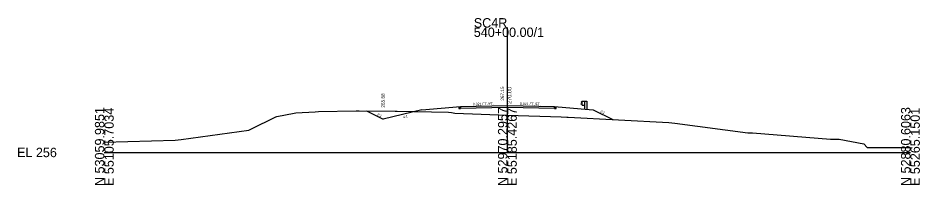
# Model space of a CAD drawing. Extents: x 9740 to 17409, y 8856 to 28416.
# Drawn here: x 11740.2 to 12008.7, y 20861.7 to 20911.5 of the extents above; entities that cross this region are included whole.
import ezdxf

# ---------------------------------------------------------------- set-up
doc = ezdxf.new("R2010")
doc.units = 0
for name, color, linetype in [('Level 10', 7, 'Continuous'), ('Level 11', 7, 'Continuous'), ('Level 12', 7, 'Continuous'), ('Level 24', 7, 'Continuous'), ('Level 32', 7, 'Continuous'), ('Level 33', 7, 'Continuous'), ('Level 59', 7, 'Continuous'), ('Level 6', 7, 'Continuous'), ('Level 60', 7, 'Continuous'), ('Level 63', 7, 'Continuous'), ('Level 7', 7, 'Continuous')]:
    doc.layers.add(name, color=color, linetype=linetype)

msp = doc.modelspace()

# ---------------------------------------------------------------- linework, layer by layer
at = {"layer": 'Level 11'}
for p, q in [((11871.85, 20884.79), (11871.35, 20884.78)), ((11871.35, 20884.78), (11871.35, 20884.44)), ((11871.35, 20884.44), (11871.85, 20884.45)), ((11871.85, 20885.09), (11871.85, 20884.79)), ((11899.85, 20884.79), (11899.85, 20885.09)), ((11900.35, 20884.78), (11899.85, 20884.79)), ((11899.85, 20884.45), (11900.35, 20884.44)), ((11900.35, 20884.44), (11900.35, 20884.78))]:
    msp.add_line(p, q, dxfattribs=at)
at = {"layer": 'Level 12'}
for p, q in [((11885.85, 20884.74), (11871.85, 20884.45)), ((11899.85, 20884.45), (11885.85, 20884.74))]:
    msp.add_line(p, q, dxfattribs=at)
at = {"layer": 'Level 24'}
for p, q in [((11908.12, 20886.6), (11907.85, 20886.4)), ((11908.12, 20885.51), (11908.12, 20886.67)), ((11908.12, 20886.67), (11908.79, 20886.67)), ((11908.79, 20886.67), (11908.79, 20884.34)), ((11908.79, 20886.67), (11909.46, 20886.67)), ((11909.46, 20886.67), (11909.46, 20884.29)), ((11907.85, 20886.4), (11907.85, 20886.35)), ((11907.85, 20886.35), (11908.12, 20886.15)), ((11907.85, 20885.83), (11908.12, 20886.03)), ((11907.85, 20885.78), (11907.85, 20885.83)), ((11908.12, 20885.58), (11907.85, 20885.78)), ((11908.12, 20885.51), (11908.79, 20885.51))]:
    msp.add_line(p, q, dxfattribs=at)
at = {"layer": 'Level 59'}
for p, q in [((11871.85, 20885.09), (11885.85, 20885.38)), ((11885.85, 20885.38), (11899.85, 20885.09))]:
    msp.add_line(p, q, dxfattribs=at)
at = {"layer": 'Level 6'}
for p, q in [((11860.36, 20884.13), (11871.85, 20885.09)), ((11899.85, 20885.09), (11907.85, 20884.42)), ((11907.85, 20884.42), (11911.35, 20884.13))]:
    msp.add_line(p, q, dxfattribs=at)
at = {"layer": 'Level 60'}
for p, q in [((11809.51, 20878.34), (11816.88, 20882.03)), ((11816.88, 20882.03), (11817.2, 20882.15)), ((11817.2, 20882.15), (11822.41, 20883.12)), ((11822.41, 20883.12), (11822.91, 20883.15)), ((11822.91, 20883.15), (11828.65, 20883.54)), ((11828.65, 20883.54), (11829.57, 20883.56)), ((11829.57, 20883.56), (11840.87, 20883.79)), ((11840.87, 20883.79), (11841.69, 20883.78)), ((11841.69, 20883.78), (11852.42, 20883.73)), ((11852.42, 20883.73), (11853.08, 20883.71)), ((11853.08, 20883.71), (11868.34, 20883.41)), ((11868.34, 20883.41), (11869.19, 20883.33)), ((11869.19, 20883.33), (11870.24, 20883.06)), ((11870.24, 20883.06), (11885.85, 20882.53)), ((11885.85, 20882.53), (11901.89, 20881.99)), ((11901.89, 20881.99), (11903.56, 20881.88)), ((11903.56, 20881.88), (11903.99, 20881.89)), ((11903.99, 20881.89), (11933.95, 20880.33)), ((11933.95, 20880.33), (11934.81, 20880.17)), ((11934.81, 20880.17), (11935.69, 20880.13)), ((11935.69, 20880.13), (11957.42, 20877.27)), ((11788.77, 20875.28), (11808.9, 20878.03)), ((11808.9, 20878.03), (11809.51, 20878.34)), ((11957.42, 20877.27), (11958.87, 20877.22)), ((11958.87, 20877.22), (11982.04, 20875.37)), ((11765.85, 20874.42), (11786.93, 20875.03)), ((11786.93, 20875.03), (11788.77, 20875.28)), ((11982.04, 20875.37), (11984.61, 20875.33)), ((11984.61, 20875.33), (11992.02, 20873.94)), ((11992.02, 20873.94), (11992.94, 20872.83)), ((11992.94, 20872.83), (12005.85, 20872.83))]:
    msp.add_line(p, q, dxfattribs=at)
at = {"layer": 'Level 63'}
for p, q in [((11885.85, 20871.38), (11885.85, 20908.62)), ((11765.85, 20871.38), (11885.85, 20871.38)), ((11885.85, 20871.38), (12005.85, 20871.38))]:
    msp.add_line(p, q, dxfattribs=at)
at = {"layer": 'Level 7'}
for p, q in [((11860.36, 20884.13), (11848.89, 20881.26)), ((11911.35, 20884.13), (11917.21, 20881.2)), ((11843.88, 20883.77), (11848.89, 20881.26))]:
    msp.add_line(p, q, dxfattribs=at)

# ---------------------------------------------------------------- texts
at = {"layer": 'Level 10'}
msp.add_text('267.15', height=1, rotation=90, dxfattribs=at).set_placement((11884.85, 20886.82))
at = {"layer": 'Level 32'}
for s, rotation, p in [('0.021 FT./FT.', 1.1916, (11875.56, 20885.42)), ('0.021 FT./FT.', 358.8084, (11889.57, 20885.55)), ('2:1', 333.435, (11913.41, 20883.41)), ('2:1', 333.435, (11846.98, 20882.52)), ('4:1', 14.0362, (11854.88, 20881.5))]:
    msp.add_text(s, height=0.75, rotation=rotation, dxfattribs=at).set_placement(p)
at = {"layer": 'Level 33'}
msp.add_text('265.88', height=1, rotation=90, dxfattribs=at).set_placement((11849.33, 20884.76))
at = {"layer": 'Level 59'}
msp.add_text(' 270.00', height=1.2, rotation=90, dxfattribs=at).set_placement((11887.05, 20885.38))
at = {"layer": 'Level 63'}
for s, p in [('SC4R', (11875.85, 20908.62)), ('540+00.00/1', (11875.85, 20905.82)), ('EL 256', (11739.85, 20869.98))]:
    msp.add_text(s, height=2.8, dxfattribs=at).set_placement(p)
for s, p in [('N 53059.9851', (11765.85, 20861.38)), ('E 55105.7034', (11768.65, 20861.38)), ('N 52970.2957', (11885.85, 20861.38)), ('E 55185.4267', (11888.65, 20861.38)), ('N 52880.6063', (12005.85, 20861.38)), ('E 55265.1501', (12008.65, 20861.38))]:
    msp.add_text(s, height=2.8, rotation=90, dxfattribs=at).set_placement(p)

doc.saveas('drawing.dxf')
